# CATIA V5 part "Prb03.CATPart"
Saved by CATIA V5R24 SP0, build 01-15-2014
Part number: Part3
Bounding box of the stored display mesh (mm): x -163 to 95, y -77.362 to 77.362, z -85 to 85
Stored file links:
  C:\Users\cdl\Downloads\2024_CAD_midterm\Prb03.CATPart
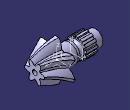
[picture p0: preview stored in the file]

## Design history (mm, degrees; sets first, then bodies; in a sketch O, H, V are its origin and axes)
AxisSystem1: origin (0, 0, 0), X (1, 0, 0), Y (0, 1, 0), Z (0, 0, 1)
Body1 (main body)
  Sketch1 on yz-plane, origin (0, 0, 0), H (0, 1, 0), V (0, 0, 1)
    arc A1 centre (0, 0) radius 50 from (-20, 45.8258) to (-29.6863, 40.2334) ccw
    arc A2 centre (-44.9945, 46.6682) radius 65 from (20, 45.8258) to (7.5, 85) ccw
    point P2 (20, 45.8258)
    point P3 (7.5, 85)
    point P4 (-7.5, 85)
    point P5 (-20, 45.8258)
    arc A3 centre (44.9945, 46.6682) radius 65 from (-20, 45.8258) to (-7.5, 85) cw
    line L1 (-7.5, 85) -> (7.5, 85)
    point P8 (-49.6863, 5.5924)
    arc A4 centre (-17.9186, 62.3005) radius 65 from (-49.6863, 5.5924) to (-77.3622, 36.0048) cw
    line L2 (-77.3622, 36.0048) -> (-69.8622, 48.9952)
    point P11 (-29.6863, 40.2334)
    arc A5 centre (-62.9132, -15.6323) radius 65 from (-29.6863, 40.2334) to (-69.8622, 48.9952) ccw
    point P14 (-29.6863, -40.2334)
    arc A6 centre (-62.9132, 15.6323) radius 65 from (-29.6863, -40.2334) to (-69.8622, -48.9952) cw
    line L3 (-69.8622, -48.9952) -> (-77.3622, -36.0048)
    point P17 (-49.6863, -5.5924)
    arc A7 centre (-17.9186, -62.3005) radius 65 from (-49.6863, -5.5924) to (-77.3622, -36.0048) ccw
    point P20 (20, -45.8258)
    arc A8 centre (-44.9945, -46.6682) radius 65 from (20, -45.8258) to (7.5, -85) cw
    line L4 (7.5, -85) -> (-7.5, -85)
    point P23 (-20, -45.8258)
    arc A9 centre (44.9945, -46.6682) radius 65 from (-20, -45.8258) to (-7.5, -85) ccw
    point P26 (49.6863, -5.5924)
    arc A10 centre (17.9186, -62.3005) radius 65 from (49.6863, -5.5924) to (77.3622, -36.0048) cw
    line L5 (77.3622, -36.0048) -> (69.8622, -48.9952)
    point P29 (29.6863, -40.2334)
    arc A11 centre (62.9132, 15.6323) radius 65 from (29.6863, -40.2334) to (69.8622, -48.9952) ccw
    point P32 (29.6863, 40.2334)
    arc A12 centre (62.9132, -15.6323) radius 65 from (29.6863, 40.2334) to (69.8622, 48.9952) cw
    line L6 (69.8622, 48.9952) -> (77.3622, 36.0048)
    point P35 (49.6863, 5.5924)
    arc A13 centre (17.9186, 62.3005) radius 65 from (49.6863, 5.5924) to (77.3622, 36.0048) ccw
    arc A14 centre (0, 0) radius 50 from (-49.6863, 5.5924) to (-49.6863, -5.5924) ccw
    arc A15 centre (0, 0) radius 50 from (-29.6863, -40.2334) to (-20, -45.8258) ccw
    arc A16 centre (0, 0) radius 50 from (20, -45.8258) to (29.6863, -40.2334) ccw
    arc A17 centre (0, 0) radius 50 from (49.6863, -5.5924) to (49.6863, 5.5924) ccw
    arc A18 centre (0, 0) radius 50 from (29.6863, 40.2334) to (20, 45.8258) ccw
    radius A1 = 50
    distance P3 H = 85
    length L1 = 15
    distance P5 P2 = 40
    radius A2 = 65
    distance P8 P11 = 40
    radius A5 = 65
    length L2 = 15
    length L3 = 15
    radius A7 = 65
    distance P14 P17 = 40
    radius A9 = 65
    length L4 = 15
    distance P20 P23 = 40
    length L5 = 15
    radius A11 = 65
    distance P26 P29 = 40
    length L6 = 15
    radius A13 = 65
    distance P32 P35 = 40
    symmetry: P3 P4 V, P2 P5 V, A2 A3 V
    horizontal: L1 H
    coincidence: A1 A14, A14 A15, A15 A16, A16 A17, A17 A18
  Plane1: type Offset, RefPlane yz-plane, Offset 45
  Sketch2 on Plane1, origin (45, 0, 0), H (0, 1, 0), V (0, 0, 1)
    arc A1 centre (0.0238, -0.0238) radius 37.5335 from (-23.3843, 29.3159) to (-29.3159, 23.3843) ccw
    arc A2 centre (-42.5426, -23.5379) radius 48.7508 from (-29.3159, 23.3843) to (-60.1219, 21.933) ccw
    line L1 (-60.1219, 21.933) -> (-63.0336, 11.0664)
    arc A3 centre (-25.074, 41.6557) radius 48.7508 from (-63.0336, 11.0664) to (-37.0805, -5.5935) ccw
    arc A4 centre (0.0325, 0.0087) radius 37.5335 from (-37.0805, -5.5935) to (-34.9094, -13.6962) ccw
    arc A5 centre (-0.8869, -48.6119) radius 48.7508 from (-34.9094, -13.6962) to (-49.0555, -41.1006) ccw
    line L2 (-49.0555, -41.1006) -> (-41.1006, -49.0555)
    arc A6 centre (-48.6119, -0.8869) radius 48.7508 from (-41.1006, -49.0555) to (-13.6962, -34.9094) ccw
    arc A7 centre (0.0087, 0.0325) radius 37.5335 from (-13.6962, -34.9094) to (-5.5935, -37.0805) ccw
    arc A8 centre (41.6557, -25.074) radius 48.7508 from (-5.5935, -37.0805) to (11.0664, -63.0336) ccw
    line L3 (11.0664, -63.0336) -> (21.933, -60.1219)
    arc A9 centre (-23.5379, -42.5426) radius 48.7508 from (21.933, -60.1219) to (23.3843, -29.3159) ccw
    arc A10 centre (-0.0238, 0.0238) radius 37.5335 from (23.3843, -29.3159) to (29.3159, -23.3843) ccw
    arc A11 centre (42.5426, 23.5379) radius 48.7508 from (29.3159, -23.3843) to (60.1219, -21.933) ccw
    line L4 (60.1219, -21.933) -> (63.0336, -11.0664)
    arc A12 centre (25.074, -41.6557) radius 48.7508 from (63.0336, -11.0664) to (37.0805, 5.5935) ccw
    arc A13 centre (-0.0325, -0.0087) radius 37.5335 from (37.0805, 5.5935) to (34.9094, 13.6962) ccw
    arc A14 centre (0.8869, 48.6119) radius 48.7508 from (34.9094, 13.6962) to (49.0555, 41.1006) ccw
    line L5 (49.0555, 41.1006) -> (41.1006, 49.0555)
    arc A15 centre (48.6119, 0.8869) radius 48.7508 from (41.1006, 49.0555) to (13.6962, 34.9094) ccw
    arc A16 centre (-0.0087, -0.0325) radius 37.5335 from (13.6962, 34.9094) to (5.5935, 37.0805) ccw
    arc A17 centre (-41.6557, 25.074) radius 48.7508 from (5.5935, 37.0805) to (-11.0664, 63.0336) ccw
    line L6 (-11.0664, 63.0336) -> (-21.933, 60.1219)
    arc A18 centre (23.5379, 42.5426) radius 48.7508 from (-21.933, 60.1219) to (-23.3843, 29.3159) ccw
  Plane2: type Offset, RefPlane yz-plane, Offset 95
  Sketch3 on Plane2, origin (95, 0, 0), H (0, 1, 0), V (0, 0, 1)
    arc A1 centre (0.0194, -0.0112) radius 25.0223 from (-20.1167, 14.8431) to (-22.9129, 10) ccw
    arc A2 centre (-23.334, -22.4978) radius 32.5005 from (-22.9129, 10) to (-42.5, 3.75) ccw
    line L1 (-42.5, 3.75) -> (-42.5, -3.75)
    arc A3 centre (-23.334, 22.4978) radius 32.5005 from (-42.5, -3.75) to (-22.9129, -10) ccw
    arc A4 centre (0.0194, 0.0112) radius 25.0223 from (-22.9129, -10) to (-20.1167, -14.8431) ccw
    arc A5 centre (7.8167, -31.4567) radius 32.5005 from (-20.1167, -14.8431) to (-24.4976, -34.9311) ccw
    line L2 (-24.4976, -34.9311) -> (-18.0024, -38.6811)
    arc A6 centre (-31.1506, -8.9589) radius 32.5005 from (-18.0024, -38.6811) to (-2.7962, -24.8431) ccw
    arc A7 centre (0, 0.0225) radius 25.0223 from (-2.7962, -24.8431) to (2.7962, -24.8431) ccw
    arc A8 centre (31.1506, -8.9589) radius 32.5005 from (2.7962, -24.8431) to (18.0024, -38.6811) ccw
    line L3 (18.0024, -38.6811) -> (24.4976, -34.9311)
    arc A9 centre (-7.8167, -31.4567) radius 32.5005 from (24.4976, -34.9311) to (20.1167, -14.8431) ccw
    arc A10 centre (-0.0194, 0.0112) radius 25.0223 from (20.1167, -14.8431) to (22.9129, -10) ccw
    arc A11 centre (23.334, 22.4978) radius 32.5005 from (22.9129, -10) to (42.5, -3.75) ccw
    line L4 (42.5, -3.75) -> (42.5, 3.75)
    arc A12 centre (23.334, -22.4978) radius 32.5005 from (42.5, 3.75) to (22.9129, 10) ccw
    arc A13 centre (-0.0194, -0.0112) radius 25.0223 from (22.9129, 10) to (20.1167, 14.8431) ccw
    arc A14 centre (-7.8167, 31.4567) radius 32.5005 from (20.1167, 14.8431) to (24.4976, 34.9311) ccw
    line L5 (24.4976, 34.9311) -> (18.0024, 38.6811)
    arc A15 centre (31.1506, 8.9589) radius 32.5005 from (18.0024, 38.6811) to (2.7962, 24.8431) ccw
    arc A16 centre (0, -0.0225) radius 25.0223 from (2.7962, 24.8431) to (-2.7962, 24.8431) ccw
    arc A17 centre (-31.1506, 8.9589) radius 32.5005 from (-2.7962, 24.8431) to (-18.0024, 38.6811) ccw
    line L6 (-18.0024, 38.6811) -> (-24.4976, 34.9311)
    arc A18 centre (7.8167, 31.4567) radius 32.5005 from (-24.4976, 34.9311) to (-20.1167, 14.8431) ccw
  Loft1: solid, Sections (Sketch1; Sketch2; Sketch3)
  Sketch4 on ZX plane of AxisSystem1, origin (0, 0, 0), H (0, 0, 1), V (1, 0, 0)
    line L1 (-45, 0) -> (-45, -5)
    line L2 (-45, -5) -> (-39, -5)
    line L3 (-39, -5) -> (-39, -51)
    point P4 (-39, -51)
    line L4 (-39, -51) -> (-38, -51)
    line L5 (-38, -51) -> (-38, -61)
    point P6 (-38, -61)
    point P7 (-32.5, -83)
    line L6 (-32.5, -163) -> (0, -163)
    point P9 (0, -163)
    line L7 (0, -163) -> (0, 0)
    line L8 (0, 0) -> (-45, 0)
    line L9 (-32.5, -83) -> (-32.5, -131)
    point P10 (-32.5, -131)
    line L10 (-32.5, -131) -> (-32.5, -131)
    point P11 (-32.5, -131)
    line L11 (-32.5, -131) -> (-32.5, -163)
    line L12 (-38, -61) -> (-32.4997, -61)
    arc A1 centre (-32.4997, -72) radius 11 from (-32.4997, -61) to (-32.5, -83) cw
    point P14 (-32.5, -83)
    distance L7 L1 = 45
    distance L3 L7 = 39
    distance L5 L7 = 38
    distance L6 P7 = 80
    distance P4 L6 = 112
    distance L2 L6 = 158
    distance L2 L8 = 5
    distance L11 L7 = 32.5
    distance P6 L6 = 102
    distance L10 L6 = 32
    radius A1 = 11
    vertical: L1 V, L3 V, L5 V, L7 V, L9 V
    horizontal: L2 H, L4 H, L6 H, L8 H, L10 H, L12 H
    coincidence: P9 V, P10 P11, P14 P7
    tangency: A1 L12
  Shaft1: profile Sketch4, axis Sketch4.V, angle 360
  Plane3: type Offset, RefPlane YZ plane of AxisSystem1, Offset -83
  Sketch5 on Plane3, origin (-83, 0, 0), H (0, 1, 0), V (0, 0, 1)
    point P1 (-25.6174, 20)
    projected circle E1 centre (0, 0) radius 38 from edge [face of Shaft1 from Sketch4.L12 | face of Shaft1 from Sketch4.L5]
    point P2 (-20, 32.311)
    arc A1 centre (0, 0) radius 38 from (-5, 37.6696) to (5, 37.6696) ccw
    point P3 (-10, 36.6606)
    arc A2 centre (0, 0) radius 43 from (5, 42.7083) to (-5, 42.7083) ccw
    line L1 (5, 37.6696) -> (5, 42.7083)
    point P4 (5, 37.6696)
    point P5 (5, 42.7083)
    point P6 (-5, 42.7083)
    point P7 (-5, 37.6696)
    line L2 (-5, 37.6696) -> (-5, 42.7083)
    distance L2 L1 = 10
    radius A1 = 38 (reference)
    radius A2 = 43
    coincidence: P2 E1, A1 P3, P3 E1, P4 E1
    vertical: L1 V
    symmetry: P5 P6 V, P4 P7 V, L1 L2 V
  Pad1: profile Sketch5, direction (-1, 0, 0), length 48
  CircPattern1: of Pad1, instances 13, angular step 27.6923 {= 360.0*1 deg/CircPattern1.AngularNumber}, axis from end face of Pad1
  Sketch6 on face of Shaft1 from Sketch4.L6, origin (-163, 0, 0), H (0, -1, 0), V (0, 0, 1)
    circle A1 centre (0, 0) radius 10
    radius A1 = 10
  Pocket1: profile Sketch6, direction (1, 0, 0), through (limit type 3)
